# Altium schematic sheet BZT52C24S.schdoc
size 127 x 101 mm
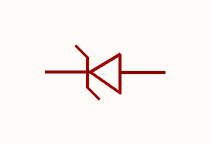
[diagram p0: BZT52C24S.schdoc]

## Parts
ZD?  bzt52c24s_c22620  [SOD-323_L1.8-W1.3-LS2.5-RD]  (value not drawn)

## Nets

Not connected (* = marked no-connect by the designer): ZD? 1(K) 2(A)

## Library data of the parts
ZD? = bzt52c24s_c22620: 二极管配置:1个独立式;稳压值(标称值):24V;稳压值(范围):22.8V~25.6V;耗散功率(Pd):200mW;; Manufacturer: CJ(江苏长电/长晶); AddInBom: yes; ModelId: db63db13d9e342eb939127d413d6200b; ModelTransform: 104.3305,51.181,0,0,0,0,0,-0.004,0; Diode Configuration: 1个独立式; Zener Voltage(Nom): 24V; Reverse Leakage Current (Ir): 100nA@16.8V; Pd - Power Dissipation: 200mW; Impedance(Zzt): 70Ω; Impedance(Zzk): 250Ω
